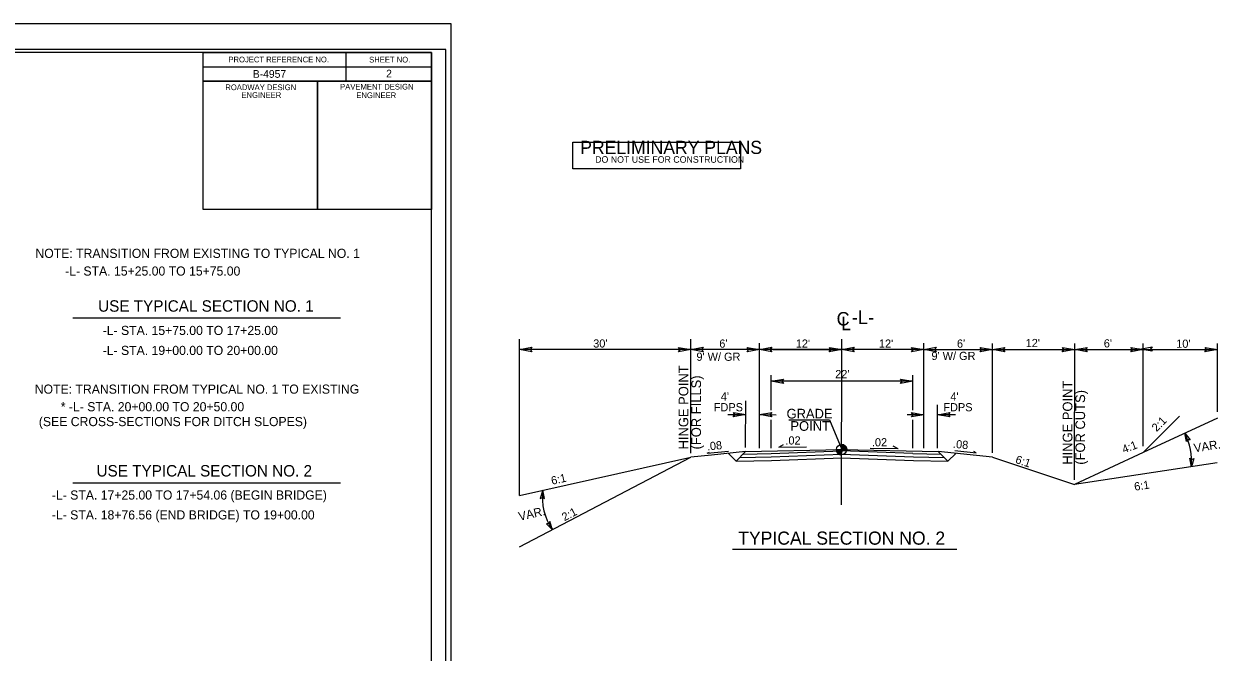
# Model space of a CAD drawing. Extents: x 1718167 to 1721223, y 797898 to 799800.
# Drawn here: x 1720176 to 1721223, y 798574 to 799124 of the extents above; entities that cross this region are included whole.
import ezdxf

# ---------------------------------------------------------------- set-up
doc = ezdxf.new("R2010")
doc.units = 0
for name, color, linetype in [('Default', 7, 'Continuous'), ('Old_Level_1', 7, 'Continuous'), ('Old_Level_2', 7, 'Continuous'), ('Prop Dimension Text', 7, 'Continuous'), ('Prop Terminator CELL', 7, 'Continuous'), ('Sheet Cutting Line CELL', 7, 'Continuous'), ('Sheet Data Field CELL', 7, 'Continuous'), ('Sheet Plot Border Inside CELL', 7, 'Continuous'), ('Sheet Plot Border Outside CELL', 7, 'Continuous'), ('Sheet Sticker Preliminary CELL', 7, 'Continuous'), ('Sheet Typical CELL', 7, 'Continuous'), ('Typical Slope Point Local CELL', 7, 'Continuous'), ('Typical Terminator CELL', 7, 'Continuous'), ('Typical Text Centerline CELL', 7, 'Continuous'), ('Typical Text Grade Point CELL', 7, 'Continuous'), ('Typical Text Label CELL', 7, 'Continuous')]:
    doc.layers.add(name, color=color, linetype=linetype)

# ---------------------------------------------------------------- blocks, each defined once
blk = doc.blocks.new('TERMINATOR')
at = {"layer": 'Typical Terminator CELL'}
blk.add_lwpolyline([(-0.469, 0.081), (0, 0), (-0.471, -0.083), (-0.411, 0)], close=True, dxfattribs=at)

msp = doc.modelspace()

# ---------------------------------------------------------------- linework, layer by layer
at = {"layer": 'Default'}
for p, q in [((1720218.9, 798867), (1720453.3, 798867)), ((1720218.9, 798722.7), (1720453.3, 798722.7))]:
    msp.add_line(p, q, dxfattribs=at)
at = {"layer": 'Old_Level_1'}
for p, q in [((1720610, 798711.6), (1720610.1, 798848.3)), ((1720760.1, 798748.4), (1720760.1, 798848.3)), ((1720820.1, 798753), (1720820.1, 798844.8)), ((1720964.1, 798753), (1720964.1, 798844.8)), ((1721024, 798748.7), (1721024.1, 798844.7)), ((1721096, 798725.3), (1721096.1, 798844.7)), ((1721156.1, 798754.8), (1721156.1, 798844.7)), ((1721221.1, 798784.6), (1721221.1, 798844.7)), ((1720760.1, 798839.3), (1720610.1, 798839.3)), ((1720820.1, 798839.3), (1720760.1, 798839.3)), ((1720892.1, 798839.3), (1720820.1, 798839.3)), ((1720832.1, 798839.3), (1720892.1, 798839.3)), ((1720964.1, 798839.2), (1720892.1, 798839.3)), ((1720964.1, 798839.2), (1721024.1, 798839.2)), ((1721024.1, 798839.2), (1721096.1, 798839.2)), ((1721096.1, 798839.2), (1721156.1, 798839.2)), ((1721156.1, 798839.2), (1721221.1, 798839.2)), ((1720830.4, 798786.1), (1720830.4, 798816.7)), ((1720954.4, 798811.5), (1720830.4, 798811.5)), ((1720954.4, 798786.1), (1720954.4, 798816.7)), ((1720808, 798753.5), (1720808.1, 798794.3)), ((1720976.1, 798753), (1720976.1, 798790.9)), ((1720792.3, 798782.3), (1720808.1, 798782.3)), ((1720820.1, 798782.3), (1720834.8, 798782.2)), ((1720964.1, 798782.2), (1720949.3, 798782.2)), ((1720991.8, 798782.2), (1720976.1, 798782.2)), ((1720830.3, 798753), (1720830.4, 798777.8)), ((1720845.9, 798777.7), (1720881.5, 798777.7)), ((1720881.5, 798777.7), (1720892.1, 798751.6)), ((1720954.3, 798753), (1720954.4, 798777.8)), ((1720778.2, 798746.9), (1720760.1, 798745)), ((1720808, 798749.9), (1720778.2, 798746.9)), ((1720887.6, 798751.6), (1720892.1, 798751.6)), ((1720892, 798747.1), (1720892.1, 798751.6)), ((1720892.1, 798751.6), (1720892, 798747.1)), ((1720892.1, 798751.6), (1720892.1, 798756.1)), ((1720896.6, 798751.6), (1720892.1, 798751.6)), ((1721024.1, 798745), (1720976.6, 798749.9)), ((1720991.1, 798750.8), (1721009.9, 798748.9)), ((1721009.9, 798748.9), (1721007.8, 798749.9)), ((1721024.1, 798745), (1721096, 798721))]:
    msp.add_line(p, q, dxfattribs=at)
for points in [[(1720887.6, 798751.6), (1720887.6, 798751.1)], [(1720887.7, 798751.6), (1720887.7, 798750.6)], [(1720887.7, 798751.6), (1720887.7, 798750.3)], [(1720887.8, 798751.6), (1720887.8, 798750)], [(1720887.9, 798751.6), (1720887.9, 798749.8)], [(1720888, 798751.6), (1720888, 798749.6)], [(1720888.1, 798751.6), (1720888.1, 798749.4)], [(1720888.2, 798751.6), (1720888.2, 798749.3)], [(1720888.3, 798751.6), (1720888.3, 798749.1)], [(1720888.4, 798751.6), (1720888.4, 798749)], [(1720888.5, 798751.6), (1720888.5, 798748.9)], [(1720888.6, 798751.6), (1720888.6, 798748.8)], [(1720888.6, 798751.6), (1720888.6, 798748.7)], [(1720888.7, 798751.6), (1720888.7, 798748.6)], [(1720888.8, 798751.6), (1720888.8, 798748.5)], [(1720888.9, 798751.6), (1720888.9, 798748.4)], [(1720889, 798751.6), (1720889, 798748.3)], [(1720889.1, 798751.6), (1720889.1, 798748.2)], [(1720889.2, 798751.6), (1720889.2, 798748.1)], [(1720889.3, 798751.6), (1720889.3, 798748.1)], [(1720889.4, 798751.6), (1720889.4, 798748)], [(1720889.5, 798751.6), (1720889.5, 798747.9)], [(1720889.5, 798751.6), (1720889.5, 798747.9)], [(1720889.6, 798751.6), (1720889.6, 798747.8)], [(1720889.7, 798751.6), (1720889.7, 798747.8)], [(1720889.8, 798751.6), (1720889.8, 798747.7)], [(1720889.9, 798751.6), (1720889.9, 798747.7)], [(1720890, 798751.6), (1720890, 798747.6)], [(1720890.1, 798751.6), (1720890.1, 798747.6)], [(1720890.2, 798751.6), (1720890.2, 798747.5)], [(1720890.3, 798751.6), (1720890.3, 798747.5)], [(1720890.4, 798751.6), (1720890.4, 798747.4)], [(1720890.4, 798751.6), (1720890.4, 798747.4)], [(1720890.5, 798751.6), (1720890.5, 798747.4)], [(1720890.6, 798751.6), (1720890.6, 798747.3)], [(1720890.7, 798751.6), (1720890.7, 798747.3)], [(1720890.8, 798751.6), (1720890.8, 798747.3)], [(1720890.9, 798751.6), (1720890.9, 798747.3)], [(1720891, 798751.6), (1720891, 798747.2)], [(1720891.1, 798751.6), (1720891.1, 798747.2)], [(1720891.2, 798751.6), (1720891.2, 798747.2)], [(1720891.3, 798751.6), (1720891.3, 798747.2)], [(1720891.3, 798751.6), (1720891.3, 798747.2)], [(1720891.4, 798751.6), (1720891.4, 798747.2)], [(1720891.5, 798751.6), (1720891.5, 798747.1)], [(1720891.6, 798751.6), (1720891.6, 798747.1)], [(1720891.7, 798751.6), (1720891.7, 798747.1)], [(1720891.8, 798751.6), (1720891.8, 798747.1)], [(1720891.9, 798751.6), (1720891.9, 798747.1)], [(1720892, 798751.6), (1720892, 798747.1), (1720892, 798747.1)], [(1720892.1, 798756.1), (1720892.1, 798756.1), (1720892.1, 798751.6)], [(1720892.2, 798756.1), (1720892.2, 798751.6)], [(1720892.3, 798756.1), (1720892.3, 798751.6)], [(1720892.4, 798756.1), (1720892.4, 798751.6)], [(1720892.5, 798756.1), (1720892.5, 798751.6)], [(1720892.5, 798756.1), (1720892.5, 798751.6)], [(1720892.6, 798756.1), (1720892.6, 798751.6)], [(1720892.7, 798756.1), (1720892.7, 798751.6)], [(1720892.8, 798756.1), (1720892.8, 798751.6)], [(1720892.9, 798756), (1720892.9, 798751.6)], [(1720893, 798756), (1720893, 798751.6)], [(1720893.1, 798756), (1720893.1, 798751.6)], [(1720893.2, 798756), (1720893.2, 798751.6)], [(1720893.3, 798755.9), (1720893.3, 798751.6)], [(1720893.4, 798755.9), (1720893.4, 798751.6)], [(1720893.4, 798755.9), (1720893.4, 798751.6)], [(1720893.5, 798755.9), (1720893.5, 798751.6)], [(1720893.6, 798755.8), (1720893.6, 798751.6)], [(1720893.7, 798755.8), (1720893.7, 798751.6)], [(1720893.8, 798755.8), (1720893.8, 798751.6)], [(1720893.9, 798755.7), (1720893.9, 798751.6)], [(1720894, 798755.7), (1720894, 798751.6)], [(1720894.1, 798755.6), (1720894.1, 798751.6)], [(1720894.2, 798755.6), (1720894.2, 798751.6)], [(1720894.3, 798755.5), (1720894.3, 798751.6)], [(1720894.3, 798755.5), (1720894.3, 798751.6)], [(1720894.4, 798755.4), (1720894.4, 798751.6)], [(1720894.5, 798755.4), (1720894.5, 798751.6)], [(1720894.6, 798755.3), (1720894.6, 798751.6)], [(1720894.7, 798755.2), (1720894.7, 798751.6)], [(1720894.8, 798755.2), (1720894.8, 798751.6)], [(1720894.9, 798755.1), (1720894.9, 798751.6)], [(1720895, 798755), (1720895, 798751.6)], [(1720895.1, 798755), (1720895.1, 798751.6)], [(1720895.2, 798754.9), (1720895.2, 798751.6)], [(1720895.2, 798754.8), (1720895.2, 798751.6)], [(1720895.3, 798754.7), (1720895.3, 798751.6)], [(1720895.4, 798754.6), (1720895.4, 798751.6)], [(1720895.5, 798754.5), (1720895.5, 798751.6)], [(1720895.6, 798754.4), (1720895.6, 798751.6)], [(1720895.7, 798754.2), (1720895.7, 798751.6)], [(1720895.8, 798754.1), (1720895.8, 798751.6)], [(1720895.9, 798754), (1720895.9, 798751.6)], [(1720896, 798753.8), (1720896, 798751.6)], [(1720896.1, 798753.7), (1720896.1, 798751.6)], [(1720896.1, 798753.5), (1720896.1, 798751.6)], [(1720896.2, 798753.3), (1720896.2, 798751.6)], [(1720896.3, 798753), (1720896.3, 798751.6)], [(1720896.4, 798752.7), (1720896.4, 798751.6)], [(1720896.5, 798752.2), (1720896.5, 798751.6)]]:
    msp.add_lwpolyline(points, dxfattribs=at)
msp.add_circle((1720892, 798751.6), 4.5, dxfattribs=at)
for start, end in [(179.9785, 269.9785), (359.9785, 89.9785)]:
    msp.add_arc((1720892, 798751.6), 4.5, start, end, dxfattribs=at)
at = {"layer": 'Old_Level_2'}
for p, q in [((1720774.2, 798748.5), (1720792.9, 798750.4)), ((1720774.2, 798748.5), (1720776.2, 798749.5)), ((1720837.1, 798753.7), (1720841.2, 798756.2)), ((1720837.1, 798753.7), (1720861.4, 798754.2)), ((1720941.4, 798752.2), (1720917.1, 798752.7)), ((1720941.4, 798752.2), (1720937.3, 798754.6))]:
    msp.add_line(p, q, dxfattribs=at)
at = {"layer": 'Prop Dimension Text'}
for centre, start, end in [((1721148.9, 798742.2), 353.644, 28.6699), ((1720679.6, 798709.8), 172.5997, 214.6638)]:
    msp.add_arc(centre, 49.6, start, end, dxfattribs=at)
at = {"layer": 'Prop Terminator CELL'}
for points in [[(1720620.9, 798837.4), (1720610.1, 798839.3), (1720620.9, 798841.2), (1720619.6, 798839.3)], [(1720749.3, 798841.1), (1720760.1, 798839.3), (1720749.2, 798837.4), (1720750.6, 798839.3)], [(1720770.9, 798837.4), (1720760.1, 798839.3), (1720770.9, 798841.2), (1720769.6, 798839.3)], [(1720809.3, 798841.1), (1720820.1, 798839.3), (1720809.2, 798837.3), (1720810.6, 798839.3)], [(1720830.9, 798837.4), (1720820.1, 798839.3), (1720830.9, 798841.2), (1720829.5, 798839.3)], [(1720881.3, 798841.1), (1720892.1, 798839.3), (1720881.2, 798837.3), (1720882.6, 798839.3)], [(1720902.9, 798837.4), (1720892.1, 798839.3), (1720902.9, 798841.2), (1720901.5, 798839.2)], [(1720953.3, 798841.1), (1720964.1, 798839.2), (1720953.2, 798837.3), (1720954.6, 798839.2)], [(1720974.9, 798837.4), (1720964.1, 798839.2), (1720974.9, 798841.2), (1720973.5, 798839.2)], [(1721013.3, 798841.1), (1721024.1, 798839.2), (1721013.2, 798837.3), (1721014.6, 798839.2)], [(1721034.9, 798837.4), (1721024.1, 798839.2), (1721034.9, 798841.1), (1721033.5, 798839.2)], [(1721085.3, 798841.1), (1721096.1, 798839.2), (1721085.2, 798837.3), (1721086.6, 798839.2)], [(1721106.9, 798837.3), (1721096.1, 798839.2), (1721106.9, 798841.1), (1721105.5, 798839.2)], [(1721145.3, 798841.1), (1721156.1, 798839.2), (1721145.2, 798837.3), (1721146.6, 798839.2)], [(1721163.8, 798837.9), (1721153, 798839.7), (1721163.8, 798841.7), (1721162.4, 798839.7)], [(1721210.3, 798841), (1721221.1, 798839.2), (1721210.2, 798837.3), (1721211.6, 798839.2)], [(1720841.2, 798809.6), (1720830.4, 798811.5), (1720841.2, 798813.4), (1720839.8, 798811.5)], [(1720943.6, 798813.3), (1720954.4, 798811.5), (1720943.5, 798809.5), (1720944.9, 798811.5)], [(1720797.3, 798784.1), (1720808.1, 798782.3), (1720797.2, 798780.3), (1720798.6, 798782.3)], [(1720830.9, 798780.4), (1720820.1, 798782.3), (1720830.9, 798784.2), (1720829.5, 798782.3)], [(1720953.3, 798784.1), (1720964.1, 798782.2), (1720953.2, 798780.3), (1720954.6, 798782.2)], [(1720986.9, 798780.4), (1720976.1, 798782.2), (1720986.9, 798784.1), (1720985.5, 798782.2)]]:
    msp.add_lwpolyline(points, close=True, dxfattribs=at)
at = {"layer": 'Sheet Cutting Line CELL'}
msp.add_line((1720550, 799124.4), (1718866, 799124.4), dxfattribs=at)
at = {"layer": 'Sheet Plot Border Inside CELL'}
msp.add_lwpolyline([(1720545.5, 799101.9), (1718879, 799101.9), (1718879, 798046.8), (1720545.5, 798046.8)], close=True, dxfattribs=at)
at = {"layer": 'Sheet Plot Border Outside CELL'}
msp.add_lwpolyline([(1720550, 799124.4), (1718866, 799124.4), (1718866, 798024.4), (1720550, 798024.4)], close=True, dxfattribs=at)
at = {"layer": 'Sheet Sticker Preliminary CELL'}
msp.add_lwpolyline([(1720656.6, 798997.4), (1720656.6, 799020.9), (1720803.6, 799020.9), (1720803.6, 798997.4)], close=True, dxfattribs=at)
at = {"layer": 'Sheet Typical CELL'}
for p, q in [((1720458, 799099.3), (1720458, 799074.3)), ((1720332.9, 799086.8), (1720533, 799086.8)), ((1720433, 799074.3), (1720433, 798961.9))]:
    msp.add_line(p, q, dxfattribs=at)
for points in [[(1720533, 799099.4), (1719033, 799099.4), (1719033, 798049.4), (1720533, 798049.4)], [(1720332.9, 799099.4), (1720533, 799099.4), (1720533, 799074.3), (1720332.9, 799074.3)], [(1720332.9, 799074.3), (1720433, 799074.3), (1720433, 798961.8), (1720332.9, 798961.8)], [(1720433, 799074.3), (1720533, 799074.3), (1720533, 798961.8), (1720433, 798961.8)]]:
    msp.add_lwpolyline(points, close=True, dxfattribs=at)
at = {"layer": 'Typical Slope Point Local CELL'}
for p, q in [((1721188, 798780.9), (1721156.1, 798749)), ((1721221.1, 798779.3), (1721156.1, 798749)), ((1720799.6, 798741.4), (1720793, 798748.3)), ((1720808, 798749.9), (1720799.6, 798741.4)), ((1720805.8, 798747.6), (1720830.3, 798748.1)), ((1720808, 798749.9), (1720892.1, 798751.6)), ((1720830.3, 798748.1), (1720892, 798750.5)), ((1720830.4, 798745.3), (1720892.2, 798747.7)), ((1720891.9, 798747.7), (1720955, 798745.3)), ((1720954.3, 798748.1), (1720892, 798750.5)), ((1720892.1, 798751.6), (1720976.6, 798749.9)), ((1720954.3, 798748.1), (1720978.8, 798747.6)), ((1720976.6, 798749.9), (1720985.1, 798741.4)), ((1720985.1, 798741.4), (1720992, 798748.3)), ((1721156.1, 798749), (1721096, 798721)), ((1720610, 798711.6), (1720760.1, 798745)), ((1720610, 798666.5), (1720760.1, 798745)), ((1720799.6, 798741.4), (1720830.5, 798742)), ((1720802.9, 798744.8), (1720830.4, 798745.3)), ((1720830.5, 798742), (1720892.3, 798744.4)), ((1720891.8, 798744.4), (1720954.9, 798742)), ((1720954.9, 798742), (1720985.1, 798741.4)), ((1720955, 798745.3), (1720981.7, 798744.7)), ((1721221, 798740.2), (1721096, 798721))]:
    msp.add_line(p, q, dxfattribs=at)
at = {"layer": 'Typical Text Centerline CELL'}
msp.add_line((1720892, 798703.3), (1720892.1, 798848.3), dxfattribs=at)
at = {"layer": 'Typical Text Label CELL'}
msp.add_line((1720796.6, 798664.5), (1720992.9, 798664.5), dxfattribs=at)

# ---------------------------------------------------------------- block references
at = {"layer": 'Prop Dimension Text'}
for p, xscale, yscale, rotation in [((1721192.5, 798766), 15.392576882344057, 22.093150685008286, 114.95593900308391), ((1721198.3, 798736.7), 15.392576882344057, 22.09315068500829, -92.46700988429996), ((1720630.4, 798716.1), 15.392576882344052, -22.093150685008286, 86.31361772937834), ((1720638.8, 798681.5), 15.392576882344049, -22.093150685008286, -59.199412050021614)]:
    msp.add_blockref('TERMINATOR', p, dxfattribs=dict(at, xscale=xscale, yscale=yscale, rotation=rotation))

# ---------------------------------------------------------------- texts
at = {"layer": 'Default'}
for s, height, p in [('NOTE: TRANSITION FROM EXISTING TO TYPICAL NO. 1', 8, (1720186.1, 798919.5)), ('-L- STA. 15+25.00 TO 15+75.00', 8, (1720212.1, 798904)), ('USE TYPICAL SECTION NO. 1', 10, (1720241, 798872.4)), ('-L- STA. 15+75.00 TO 17+25.00', 8, (1720245, 798852)), ('-L- STA. 19+00.00 TO 20+00.00', 8, (1720245, 798834.5)), ('NOTE: TRANSITION FROM TYPICAL NO. 1 TO EXISTING', 8, (1720185.5, 798800.6)), ('* -L- STA. 20+00.00 TO 20+50.00', 8, (1720208.3, 798785.2)), ('(SEE CROSS-SECTIONS FOR DITCH SLOPES)', 8, (1720189.1, 798772.2)), ('USE TYPICAL SECTION NO. 2', 10, (1720239.6, 798728.1)), ('-L- STA. 17+25.00 TO 17+54.06 (BEGIN BRIDGE)', 8, (1720200.5, 798707.9)), ('-L- STA. 18+76.56 (END BRIDGE) TO 19+00.00', 8, (1720200.5, 798690.5))]:
    msp.add_text(s, height=height, dxfattribs=at).set_placement(p)
at = {"layer": 'Old_Level_1'}
for s, rotation, p in [("30'", 359.988, (1720674.5, 798841)), ("6'", 359.988, (1720784.9, 798840.9)), ("12'", 359.988, (1720851.9, 798840.9)), ("12'", 359.988, (1720924.7, 798840.9)), ("6'", 359.988, (1720993, 798840.9)), ("12'", 359.988, (1721053.2, 798841.4)), ("6'", 359.988, (1721121.6, 798841.1)), ("10'", 359.988, (1721185, 798840.8)), ("9' W/ GR", 359.988, (1720764.9, 798829.4)), ("9' W/ GR", 359.988, (1720970.7, 798830.1)), ("22'", 359.988, (1720886.4, 798814.2)), (" 4' ", 359.988, (1720783.6, 798794.6)), (" 4' ", 359.9878, (1720984.6, 798794.6)), ('FDPS', 359.988, (1720780.1, 798785.2)), ('FDPS', 359.9878, (1720981.1, 798785.2))]:
    msp.add_text(s, height=7.16, rotation=rotation, dxfattribs=at).set_placement(p)
at = {"layer": 'Old_Level_2'}
for rotation, p in [(5.7484, (1720774.4, 798750.8)), (354.2008, (1720989.3, 798753.3))]:
    msp.add_text('.08 ', height=7.16, rotation=rotation, dxfattribs=at).set_placement(p)
at = {"layer": 'Prop Dimension Text'}
for s, height, rotation, p in [('GRADE', 8.47, 359.988, (1720843.8, 798778.9)), ('POINT', 8.47, 359.988, (1720847.2, 798768.1)), ('.02', 7.16, 359.988, (1720842.8, 798756.1)), ('.02', 7.16, 359.988, (1720918.5, 798754.5)), ('6:1', 7.16, 341.5531, (1721043.6, 798740.1))]:
    msp.add_text(s, height=height, rotation=rotation, dxfattribs=at).set_placement(p)
at = {"layer": 'Sheet Data Field CELL'}
for s, p in [('B-4957', (1720376.5, 799077.2)), ('2', (1720493.2, 799077.5))]:
    msp.add_text(s, height=6.75, rotation=360, dxfattribs=at).set_placement(p)
at = {"layer": 'Sheet Sticker Preliminary CELL'}
for s, height, p in [('PRELIMINARY PLANS', 11.52, (1720663.1, 799010.5)), ('DO NOT USE FOR CONSTRUCTION', 5.76, (1720676.2, 799002.8))]:
    msp.add_text(s, height=height, dxfattribs=at).set_placement(p)
at = {"layer": 'Sheet Typical CELL'}
for s, p in [('PROJECT REFERENCE NO.', (1720355.1, 799090.7)), ('SHEET NO.', (1720478.3, 799090.6)), ('ROADWAY DESIGN', (1720352.4, 799066.4)), ('PAVEMENT DESIGN', (1720452.9, 799066.9)), ('ENGINEER', (1720366.5, 799059.6)), ('ENGINEER', (1720467.1, 799059.4))]:
    msp.add_text(s, height=5, rotation=360, dxfattribs=at).set_placement(p)
at = {"layer": 'Typical Slope Point Local CELL'}
for s, height, rotation, p in [('HINGE POINT', 8.467, 90, (1720757.8, 798751.8)), ('(FOR FILLS)', 8.467, 90, (1720768.9, 798751.8)), ('HINGE POINT', 8.467, 90, (1721094.1, 798738.4)), ('(FOR CUTS)', 8.47, 90, (1721105.2, 798738.4)), ('2:1', 7.16, 44.9549, (1721167.8, 798766.8)), ('4:1', 7.16, 21.2393, (1721139.2, 798748.2)), ('VAR. ', 7.56, 8.7105, (1721201, 798749.2)), ('6:1', 7.16, 12.559, (1720638.5, 798720.8)), ('6:1', 7.16, 8.7105, (1721148.8, 798715.6)), ('VAR. ', 7.56, 12.559, (1720610, 798689.3)), ('2:1', 7.16, 27.6461, (1720649.3, 798688.8))]:
    msp.add_text(s, height=height, rotation=rotation, dxfattribs=at).set_placement(p)
at = {"layer": 'Typical Text Centerline CELL'}
msp.add_text('C', height=11.8, dxfattribs=at).set_placement((1720887.6, 798860.3))
msp.add_text('L', height=11.8, rotation=359.9469, dxfattribs=at).set_placement((1720891.5, 798856.2))
at = {"layer": 'Typical Text Grade Point CELL'}
msp.add_text('-L-', height=12, dxfattribs=at).set_placement((1720900.9, 798861.5))
at = {"layer": 'Typical Text Label CELL'}
msp.add_text('TYPICAL SECTION NO. 2', height=11.5, dxfattribs=at).set_placement((1720801.5, 798668.4))

doc.saveas('drawing.dxf')
